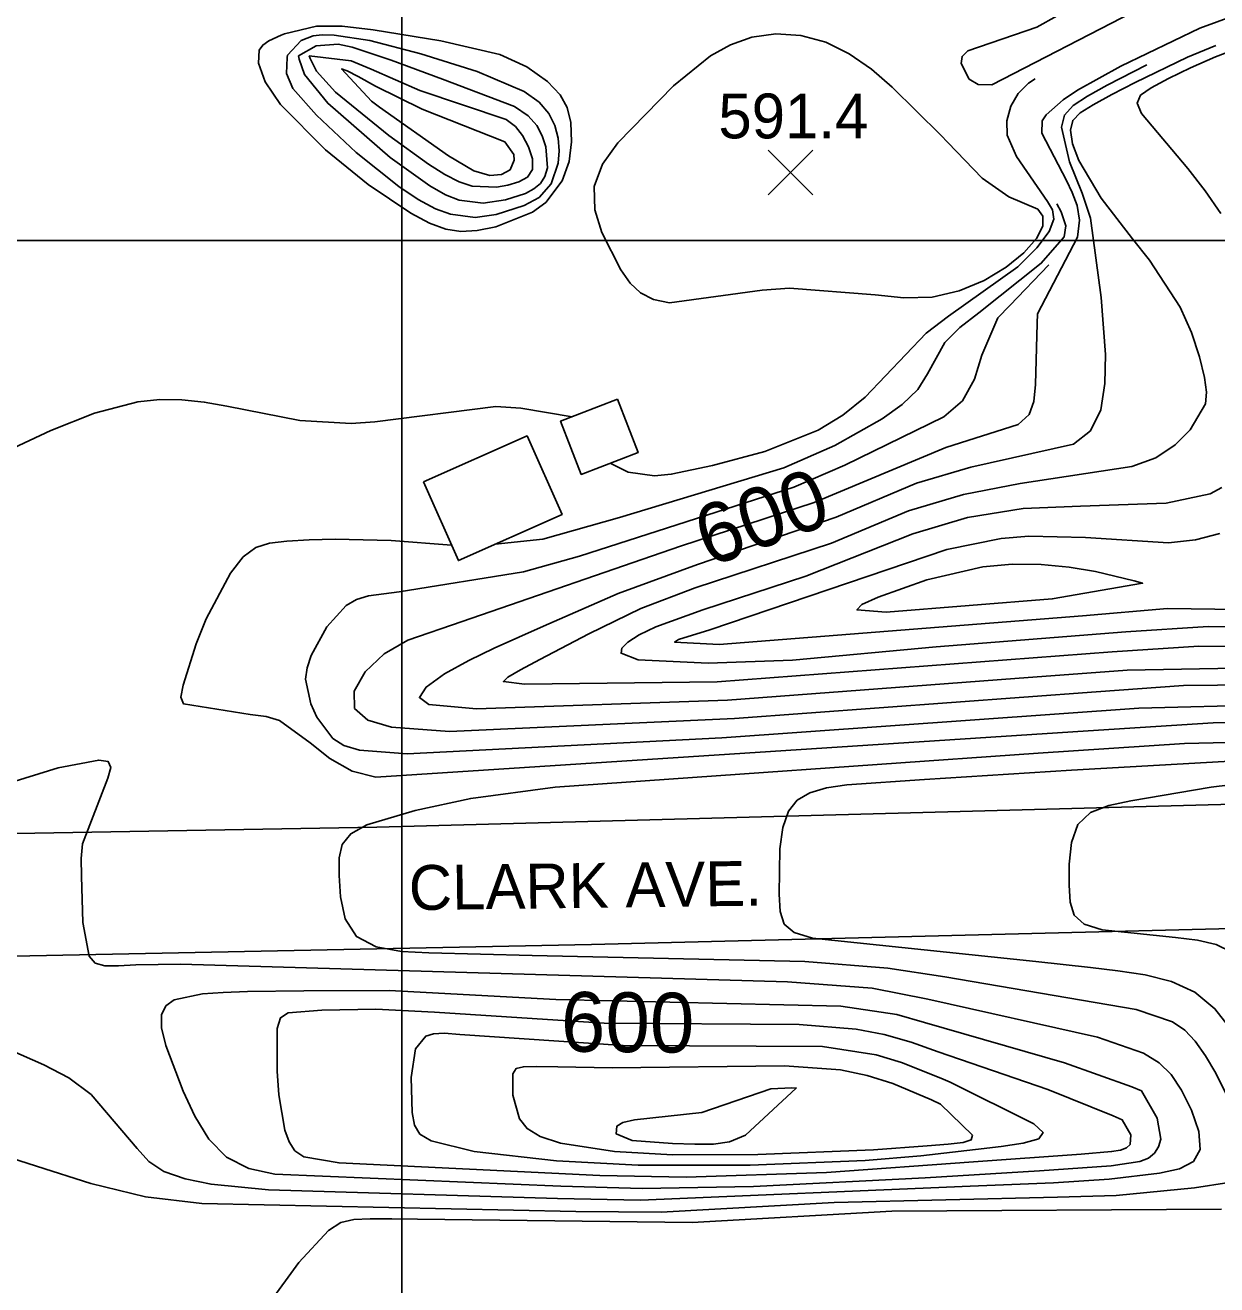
# Model space of a CAD drawing. Extents: x 79600 to 91800, y 75600 to 84400.
# Drawn here: x 88873.9 to 89272.7, y 78650.5 to 79072.1 of the extents above; entities that cross this region are included whole.
import ezdxf

# ---------------------------------------------------------------- set-up
doc = ezdxf.new("R2010")
doc.units = 0
for name, color, linetype in [('080-090$0$BLDG', 7, 'Continuous'), ('080-090$0$GRID', 7, 'Continuous'), ('080-090$0$INDEX', 7, 'Continuous'), ('080-090$0$INDXLBL', 7, 'Continuous'), ('080-090$0$INTER', 7, 'Continuous'), ('080-090$0$ROAD', 7, 'Continuous'), ('080-090$0$ROAD-NAME', 7, 'Continuous'), ('080-090$0$SPOTMARK', 7, 'Continuous'), ('080-090$0$SPOTS', 7, 'Continuous')]:
    doc.layers.add(name, color=color, linetype=linetype)

# ---------------------------------------------------------------- blocks, each defined once
blk = doc.blocks.new('080-090$0$SPOTS')
at = {"layer": '080-090$0$SPOTMARK'}
for p, q in [((-0.5, -0.5), (0.5, 0.5)), ((-0.5, 0.5), (0.5, -0.5))]:
    blk.add_line(p, q, dxfattribs=at)

msp = doc.modelspace()

# ---------------------------------------------------------------- linework, layer by layer
at = {"layer": '080-090$0$BLDG'}
for points in [[(89072.14, 78946.92), (89079.02, 78929.06), (89059.99, 78921.73), (89053.11, 78939.59)], [(89007.19, 78919.22), (89041.87, 78934.65), (89053.56, 78908.38), (89018.88, 78892.94)]]:
    msp.add_lwpolyline(points, close=True, dxfattribs=at)
at = {"layer": '080-090$0$GRID'}
for p, q in [((89000, 80000), (89000, 76000)), ((90000, 79000), (85000, 79000))]:
    msp.add_line(p, q, dxfattribs=at)
at = {"layer": '080-090$0$INDEX'}
for points in [[(89285.63, 79077.87), (89266.97, 79071.07), (89240.5, 79058.4), (89226.1, 79050.37), (89221.21, 79047.13), (89215.59, 79042.1), (89214.27, 79040.06), (89214.07, 79035.95), (89222.31, 79020.15), (89224.22, 79016.07), (89225.92, 79011.71), (89226.76, 79006.83), (89226.02, 79001.16), (89212.63, 78975.55), (89212.56, 78972.3), (89211.96, 78951.9), (89211.45, 78946.13), (89209.85, 78941.76), (89206.14, 78938.44), (89181.94, 78930.81), (89137.99, 78912.32), (89093.21, 78897.79), (89020.2, 78872.5), (89002, 78866.26), (88994.09, 78861.71), (88987.74, 78855.7), (88984.01, 78849.19), (88984.08, 78843.46), (88988.64, 78839.51), (88996.53, 78837.19), (89015.94, 78835.72), (89111.31, 78840.08), (89232.31, 78849.01), (89261.46, 78851.13), (89329.65, 78851.75)], [(89289.84, 78819.39), (89270.82, 78817.11), (89243.9, 78812.55), (89236.48, 78810.96), (89230.44, 78808.61), (89226.2, 78804.63), (89223.99, 78798.53), (89223.26, 78791.3), (89223.27, 78784.27), (89223.58, 78778.56), (89224.91, 78774.26), (89228.27, 78771.23), (89234.3, 78769.3), (89258.84, 78766.76), (89266.18, 78765.87), (89272.47, 78764.44), (89288.15, 78756.75)]]:
    msp.add_lwpolyline(points, dxfattribs=at)
for points in [[(88969.28, 79060.91), (88971.4, 79056.71), (88977.77, 79049.66), (88995.62, 79035.2), (89008.86, 79025.61), (89014.38, 79022.11), (89019.16, 79019.67), (89023.49, 79018.22), (89031.6, 79017.9), (89035.46, 79018.59), (89039.09, 79019.63), (89042.03, 79021.25), (89043.68, 79023.77), (89043.66, 79027.34), (89042.36, 79031.39), (89040.37, 79035.18), (89038.04, 79038.18), (89034.85, 79040.54), (89006.04, 79050.22), (88989.7, 79057.36), (88982.96, 79060.18), (88969.01, 79061.82)], [(89245.01, 78886.14), (89232.03, 78889.25), (89223.24, 78890.74), (89213.84, 78891.61), (89204.16, 78891.68), (89194.42, 78890.83), (89175.65, 78886.48), (89159.32, 78880.72), (89153.9, 78878.2), (89152.24, 78876.43), (89162.07, 78875.68), (89217.58, 78880.07), (89247.84, 78885.32)], [(89238, 78707.06), (89216.1, 78715.86), (89179.41, 78728.56), (89170.44, 78731.71), (89161.33, 78734.32), (89151.94, 78736.1), (89132.89, 78737.71), (89067.64, 78738.16), (89010.92, 78741.8), (88991.29, 78742.85), (88973.19, 78742.51), (88961.89, 78741.52), (88959.37, 78739.95), (88958.23, 78736.31), (88958.21, 78722.07), (88958.86, 78714.17), (88960.85, 78702.35), (88962.27, 78698.36), (88964.18, 78695.43), (88967.16, 78693.39), (88978.96, 78691.36), (89066.24, 78687.12), (89095.15, 78686.6), (89142.04, 78688.15), (89191.22, 78691.66), (89227.24, 78694.31), (89237.44, 78695.11), (89240.46, 78695.64), (89242.49, 78696.4), (89243.65, 78697.47), (89243.85, 78700.74), (89241.03, 78705.73)]]:
    msp.add_lwpolyline(points, close=True, dxfattribs=at)
at = {"layer": '080-090$0$INTER'}
for points in [[(89219.23, 79075.25), (89212.47, 79071.38), (89189.39, 79063.51), (89187.44, 79061.65), (89187.12, 79059.32), (89189.85, 79054.04), (89192.84, 79052.22), (89197.37, 79052.14), (89244.55, 79076.42)], [(89272.31, 79065.3), (89262.87, 79061.4), (89245.37, 79052.95), (89237.57, 79048.92), (89231.24, 79045.47), (89226.9, 79042.77), (89224.46, 79040.2), (89223.7, 79036.95), (89224.41, 79032.41), (89226.45, 79026.81), (89233.93, 79014.17), (89244.47, 79000.62), (89250.18, 78993.42), (89260.43, 78977.74), (89264.16, 78969.24), (89266.83, 78961.09), (89268.51, 78954.22), (89269.23, 78949.24), (89268.82, 78945.35), (89263.69, 78936.63), (89258.76, 78931.61), (89252.26, 78927.31), (89244.28, 78924.41), (89206.86, 78918.69), (89187.91, 78915), (89169.45, 78909.57), (89143.72, 78898.76), (89098.14, 78883.76), (89079.95, 78876.88), (89062.54, 78868.46), (89046.11, 78859.8), (89039.69, 78856.33), (89035.44, 78853.91), (89033.93, 78852.44), (89040.98, 78851.53), (89105.52, 78852.3), (89237.67, 78862.41), (89266.68, 78864.31), (89313.7, 78863.92)], [(89289.89, 79068.21), (89272.25, 79061.54), (89263.89, 79057.85), (89256.46, 79054.28), (89250.66, 79051.16), (89247.11, 79048.63), (89246, 79046.04), (89247.43, 79042.56), (89262.96, 79024.17), (89268.81, 79016.68), (89273.99, 79009.1)], [(89249.22, 79058.78), (89236.01, 79052.05), (89229.35, 79048.33), (89224.55, 79045.18), (89221.68, 79041.99), (89220.71, 79037.93), (89223.38, 79026.39), (89227.59, 79015.89), (89230.41, 79007.53), (89233.92, 78980.93), (89235.36, 78961.86), (89235.24, 78952.15), (89233.83, 78943.36), (89230.44, 78936.38), (89224.66, 78931.85), (89190.34, 78924.18), (89172.2, 78918.78), (89145.28, 78907.43), (89098.95, 78891.63), (89072.38, 78881.85), (89047.41, 78870.94), (89030.81, 78863.56), (89022.42, 78859.47), (89014.29, 78854.98), (89008.1, 78850.61), (89005.87, 78847.05), (89008.95, 78844.79), (89024.96, 78843.35), (89108.97, 78846.19), (89205.1, 78853.46), (89242.68, 78856.27), (89327.54, 78857.79)], [(89211.91, 79054.16), (89209.62, 79052.69), (89206.15, 79049.24), (89203.79, 79045.05), (89202.43, 79040.13), (89202.55, 79035.28), (89205.66, 79028.13), (89215.98, 79013.07), (89217.68, 79010.25), (89218.18, 79007.14), (89216.6, 79003.04), (89212.4, 78997.54), (89206.13, 78991.28), (89182.9, 78974.77), (89175.43, 78969.05), (89155.05, 78947.56), (89147.48, 78941.53), (89139.26, 78936.61), (89121.38, 78929.45), (89103.94, 78924.79), (89090.11, 78921.8), (89084.51, 78921.31), (89075.7, 78922.56), (89069.72, 78925.48)], [(89219.14, 79012.34), (89220.53, 79009.67), (89222.1, 79005), (89221.57, 79001.3), (89213.9, 78992.44), (89193.07, 78975.84), (89186.66, 78970.9), (89181.68, 78965.95), (89175.89, 78955.43), (89172.57, 78950.17), (89167.4, 78945.13), (89160.65, 78940.34), (89144.8, 78931.43), (89127.78, 78923.93), (89072.82, 78907.39), (89047.12, 78900.13), (89031.24, 78898.44)], [(89216.47, 78991.87), (89203.43, 78978.31), (89199.44, 78974.13), (89194.08, 78961.64), (89191.57, 78953.66), (89187.6, 78946.4), (89181.35, 78940.98), (89148.21, 78924.89), (89131.1, 78917.45), (89059.45, 78894.44), (89040.71, 78889.12), (88999.05, 78882.49), (88988.84, 78881.11), (88984.84, 78879.88), (88981.3, 78877.91), (88974.82, 78870.71), (88969.68, 78861.16), (88968.26, 78857), (88967.76, 78853.18), (88969.53, 78844.93), (88971.57, 78840.54), (88976.89, 78833.37), (88980.58, 78831.02), (88985.81, 78829.45), (89001.71, 78828.28), (89107.02, 78833.6), (89246.53, 78843.53), (89333.8, 78845.76)], [(89056.95, 78941.07), (89039.79, 78943.92), (89031.44, 78944.43), (88990.98, 78939.35), (88983.06, 78938.77), (88965.84, 78939.85), (88941.36, 78944.61), (88933.83, 78945.98), (88926.38, 78946.74), (88918.98, 78946.79), (88911.64, 78946.04), (88897.1, 78942.22), (88882.53, 78936.43), (88868.2, 78929.75)], [(89274.33, 78917.36), (89270.46, 78915.22), (89255.74, 78912.15), (89227.05, 78911.1), (89207.87, 78910.3), (89189.19, 78907.29), (89170.9, 78901.9), (89135.18, 78887.74), (89100.66, 78876.42), (89085.01, 78870.71), (89079.43, 78868.05), (89075.64, 78865.65), (89073.59, 78863.59), (89073.31, 78861.93), (89079.01, 78859.73), (89102.52, 78858.6), (89130.68, 78859.6), (89178.7, 78864.11), (89242.17, 78869.09), (89269.76, 78870.85), (89316.03, 78870.05)], [(89273.68, 78901.93), (89265.5, 78899.9), (89256.46, 78898.89), (89228.67, 78900.7), (89209.8, 78901.06), (89200.45, 78900.28), (89182.31, 78896.68), (89103.02, 78869.72), (89092.49, 78866.5), (89091.25, 78865.67), (89106.16, 78864.85), (89227.7, 78874.42), (89256.18, 78876.86), (89319.4, 78876)], [(89016.59, 78898.11), (88996.41, 78899.67), (88977.63, 78900.1), (88968.95, 78899.83), (88961.53, 78899.39), (88955.74, 78898.77), (88951.09, 78897.29), (88946.9, 78894.14), (88942.63, 78888.75), (88934.5, 78873.46), (88931.17, 78865.1), (88926.79, 78851.21), (88926.07, 78847.22), (88926.94, 78844.95), (88949.26, 78841.37), (88954.56, 78840.72), (88959.05, 78839.37), (88969.34, 78831.95), (88975.93, 78826.73), (88983.3, 78822.48), (88991.27, 78820.4), (89233.09, 78836.19), (89271.42, 78838.63), (89319.74, 78839.24)], [(89279.1, 78707.49), (89272.32, 78721.33), (89268.85, 78727.2), (89265.41, 78732.06), (89261.91, 78735.78), (89257.84, 78738.6), (89245.71, 78742.73), (89181.61, 78753.61), (89162.6, 78756.57), (89134.81, 78758.7), (89043.57, 78760.75), (89009, 78761.62), (88999.85, 78762.12), (88991.36, 78763.63), (88984.79, 78767.08), (88981.03, 78773.04), (88979.44, 78780.39), (88978.98, 78787.58), (88978.96, 78793.42), (88979.95, 78797.94), (88982.86, 78801.52), (88988.31, 78804.47), (89004.43, 78809.28), (89023, 78813.32), (89051.25, 78817.13), (89212.9, 78828.42), (89261.84, 78831.66), (89329.2, 78833.26)], [(88845.89, 78739.21), (88880.23, 78724.12), (88888.57, 78719.87), (88896, 78714.22), (88911.41, 78696.19), (88915.27, 78691.86), (88920.3, 78688.48), (88927.42, 78685.96), (88936.15, 78684.19), (88955.34, 78682.33), (89052.09, 78679.48), (89079.86, 78678.83), (89190.08, 78683.54), (89218.03, 78684.63), (89236.59, 78685.9), (89253.5, 78687.95), (89260.13, 78689.4), (89264.84, 78691.77), (89267.09, 78695.81), (89266.59, 78701.89), (89264.15, 78708.98), (89260.82, 78715.68), (89257.38, 78720.91), (89253.39, 78724.87), (89248.14, 78728.06), (89232.75, 78733.42), (89175.95, 78746.12), (89157.34, 78749.83), (89128.99, 78751.94), (88925.94, 78757.82), (88910.98, 78757.61), (88905.15, 78757.27), (88900.6, 78757.32), (88897.39, 78758.22), (88895.31, 78760.58), (88893.28, 78771.85), (88892.73, 78787.32), (88892.71, 78793.24), (88893.15, 78798.17), (88901.61, 78820.08), (88902.58, 78823.67), (88901.73, 78825.64), (88898.53, 78826.13), (88884.95, 78823.54), (88846.42, 78811.65)], [(89288.89, 78826.49), (89224.09, 78822.74), (89174.85, 78819.66), (89148.9, 78817.82), (89142.09, 78816.83), (89136.51, 78815.24), (89132.29, 78812.76), (89129.31, 78809.01), (89127.44, 78803.62), (89126.49, 78796.48), (89126.22, 78781.24), (89126.52, 78775.47), (89127.86, 78771.28), (89131.26, 78768.4), (89137.4, 78766.55), (89212.07, 78758.7), (89230.36, 78756.74), (89239.54, 78755.62), (89248.7, 78754.25), (89257.46, 78752.07), (89265.34, 78748.43), (89272.03, 78742.93), (89289.01, 78721.16)], [(88850.8, 78698.84), (88877.76, 78690.28), (88895.94, 78684.5), (88914.19, 78680.01), (88933.09, 78677.8), (89058.22, 78675.11), (89086.69, 78674.88), (89144.6, 78678.11), (89219.38, 78679.93), (89239, 78680.49), (89265.24, 78683), (89276.73, 78684.84)], [(89274.23, 78675.85), (89163.96, 78675.21), (89097.15, 78671.4), (89014.4, 78672.38), (89005.26, 78672.55), (88996.65, 78672.63), (88989.37, 78672.62), (88983.9, 78672.4), (88979.56, 78671.36), (88975.4, 78668.77), (88965.49, 78658.02), (88955.33, 78644.1)]]:
    msp.add_lwpolyline(points, dxfattribs=at)
for points in [[(88959.58, 79068.77), (88955.43, 79066.86), (88953.45, 79065.44), (88952.25, 79063.76), (88952.06, 79059.35), (88954.25, 79053.19), (88959.34, 79045.53), (88974.39, 79030.43), (88988.67, 79018.74), (89002.99, 79009.16), (89009.27, 79005.87), (89014.67, 79003.86), (89019.73, 79003.06), (89025.16, 79003.35), (89031.42, 79004.6), (89043.69, 79009.47), (89048.15, 79012.79), (89053.56, 79019.96), (89055.95, 79026.48), (89056.74, 79033.1), (89056.55, 79039.57), (89055.34, 79044.52), (89052.97, 79048.8), (89048.73, 79053.3), (89041.79, 79058.16), (89032.79, 79062.24), (89013.03, 79066.82), (88990.37, 79070.54), (88979.96, 79071.77), (88971.47, 79071.73), (88960.66, 79069.2)], [(89180.3, 79035.29), (89164.05, 79051.38), (89157.07, 79057.33), (89149.67, 79062.5), (89141.81, 79066.4), (89133.49, 79068.63), (89125.11, 79069.17), (89117.13, 79068.11), (89109.91, 79065.57), (89103.29, 79061.82), (89090.82, 79051.76), (89072.19, 79032.74), (89067.09, 79025.63), (89064.27, 79018.13), (89064.52, 79010.32), (89066.94, 79002.69), (89073.27, 78990.17), (89076.33, 78985.76), (89079.84, 78982.5), (89084.2, 78980.32), (89089.53, 78979.23), (89120.49, 78983.42), (89129.68, 78984.07), (89158.33, 78981.86), (89167.94, 78980.9), (89177.38, 78981.13), (89186.47, 78983.15), (89194.87, 78986.67), (89202.21, 78991.11), (89208.13, 78995.93), (89212.32, 79000.66), (89214.47, 79004.85), (89214.46, 79008.14), (89212.76, 79010.54), (89203.11, 79014.66), (89194.18, 79020.86), (89182.61, 79032.86)], [(88961.57, 79061.23), (88961.34, 79055.92), (88963.45, 79050.94), (88971.38, 79042), (88984.73, 79029.54), (88998.98, 79018.06), (89005.48, 79013.72), (89011.2, 79010.69), (89016.2, 79008.84), (89024.56, 79007.75), (89031.57, 79008.79), (89040.86, 79011.78), (89045.96, 79014.45), (89049.94, 79019.02), (89052.29, 79025.94), (89052.62, 79030.01), (89052.28, 79034.26), (89051.18, 79038.49), (89049.19, 79042.52), (89045.91, 79046.34), (89040.85, 79049.95), (89025.15, 79056.61), (89006.29, 79062.56), (88989.26, 79067), (88977.36, 79068.79), (88973.31, 79068.87), (88970.32, 79068.58), (88966.31, 79066.93), (88961.72, 79062.01)], [(88965.56, 79060.72), (88967.44, 79055.57), (88975.2, 79045.98), (88996.01, 79027.8), (89009.3, 79018.31), (89014.63, 79015.36), (89019.19, 79013.56), (89027.23, 79012.53), (89034.68, 79013.64), (89041.36, 79015.77), (89044.12, 79017.28), (89046.31, 79019.16), (89047.85, 79021.49), (89048.68, 79024.35), (89048.15, 79031.39), (89046.97, 79035.07), (89045.17, 79038.52), (89042.26, 79041.75), (89037.61, 79044.85), (89013.53, 79054.07), (88996.41, 79060.4), (88983.33, 79064.78), (88978.61, 79065.74), (88971.34, 79065.15), (88965.41, 79061.83)], [(88992.55, 79044.63), (89015.56, 79028.34), (89024.03, 79023.37), (89029.38, 79021.74), (89033.26, 79022.08), (89036.24, 79023.73), (89037.55, 79026.88), (89037.41, 79028.82), (89034.39, 79033.05), (89006.74, 79043.97), (88991.15, 79051.7), (88985.41, 79054.9), (88981.62, 79056.86), (88979.83, 79057.44), (88989.82, 79046.63)], [(89244.24, 78716.75), (89221.68, 78724.79), (89174.87, 78738.38), (89165.61, 78740.97), (89146.9, 78743.83), (89051.5, 78746.04), (88995.78, 78748.99), (88967.13, 78748.97), (88948.38, 78748.67), (88940.16, 78748.4), (88933.3, 78747.95), (88923.74, 78745.9), (88920.97, 78743.91), (88919.56, 78740.91), (88919.56, 78736.54), (88920.95, 78730.6), (88926.78, 78715.36), (88930.65, 78707.04), (88935.37, 78699.34), (88941.34, 78693.27), (88948.8, 78689.51), (88957.45, 78687.62), (89053.19, 78683.58), (89080.35, 78682.73), (89117.63, 78683.46), (89175.07, 78686.4), (89213.32, 78688.74), (89237.27, 78690.36), (89246.93, 78691.8), (89249.81, 78692.98), (89251.81, 78694.59), (89253.19, 78696.69), (89253.89, 78699.34), (89252.65, 78706.28), (89247.41, 78715.43)], [(89180.32, 78719.7), (89167.21, 78724.9), (89158.64, 78727.5), (89140.7, 78730.28), (89074, 78730.6), (89019.39, 78734.31), (89014.15, 78734.71), (89010.53, 78734.57), (89007.97, 78733.77), (89004.54, 78729.51), (89003.13, 78719.93), (89003.41, 78708.24), (89004.16, 78704.03), (89006.01, 78701), (89009.8, 78698.72), (89024.18, 78695.19), (89051.77, 78692.02), (89079.02, 78690.58), (89116.53, 78690.58), (89154.95, 78692.19), (89173.57, 78693.68), (89191.97, 78695.78), (89200.48, 78696.88), (89207.92, 78697.99), (89213.06, 78699.4), (89214.52, 78701.49), (89211.49, 78704.47), (89183.42, 78718.36)], [(89177.19, 78712.4), (89164.22, 78717.87), (89155.65, 78720.61), (89146.69, 78722.46), (89128.03, 78723.84), (89070.3, 78723.16), (89052.13, 78723.48), (89045.19, 78723.59), (89040.66, 78723.54), (89038.17, 78722.89), (89037.06, 78721.15), (89037.12, 78714), (89039.33, 78706.05), (89041.85, 78702.83), (89046.26, 78700.15), (89053.07, 78698), (89071.17, 78695.17), (89090.53, 78694.05), (89119.12, 78694.13), (89157.83, 78695.72), (89175.76, 78697.02), (89182.78, 78697.64), (89187.74, 78698.19), (89190.47, 78699.05), (89190.89, 78700.64), (89180.25, 78710.95)], [(89130.48, 78716.5), (89123.45, 78716.1), (89100.34, 78708.21), (89077.86, 78705.76), (89073.86, 78704.85), (89071.96, 78703.65), (89071.7, 78701.02), (89076.99, 78698.89), (89090.57, 78697.82), (89097.97, 78697.58), (89104.22, 78697.58), (89109.64, 78698.35), (89114.91, 78700.58), (89131.96, 78716.36)]]:
    msp.add_lwpolyline(points, close=True, dxfattribs=at)
at = {"layer": '080-090$0$ROAD'}
for p, q in [((89306.48, 78812.16), (88991.56, 78803.71)), ((88991.56, 78803.71), (88839.1, 78801.07)), ((89063.4, 78764.44), (89282.88, 78769.88)), ((88845.31, 78760.04), (89063.4, 78764.44))]:
    msp.add_line(p, q, dxfattribs=at)

# ---------------------------------------------------------------- block references
at = {"layer": '080-090$0$SPOTMARK', "xscale": 15, "yscale": 15}
msp.add_blockref('080-090$0$SPOTS', (89130.03, 79022.8), dxfattribs=at)

# ---------------------------------------------------------------- texts
at = {"layer": '080-090$0$INDXLBL'}
for rotation, p in [(19.6718, (89102.6, 78890.62)), (359.4731, (89053.13, 78728.62))]:
    msp.add_text('600', height=20, rotation=rotation, dxfattribs=at).set_placement(p)
at = {"layer": '080-090$0$ROAD-NAME'}
msp.add_text('CLARK AVE.', height=15, rotation=0.7436, dxfattribs=at).set_placement((89002.4, 78775.93))
at = {"layer": '080-090$0$SPOTS'}
msp.add_text('591.4', height=15, dxfattribs=at).set_placement((89105.87, 79034.22))

doc.saveas('drawing.dxf')
